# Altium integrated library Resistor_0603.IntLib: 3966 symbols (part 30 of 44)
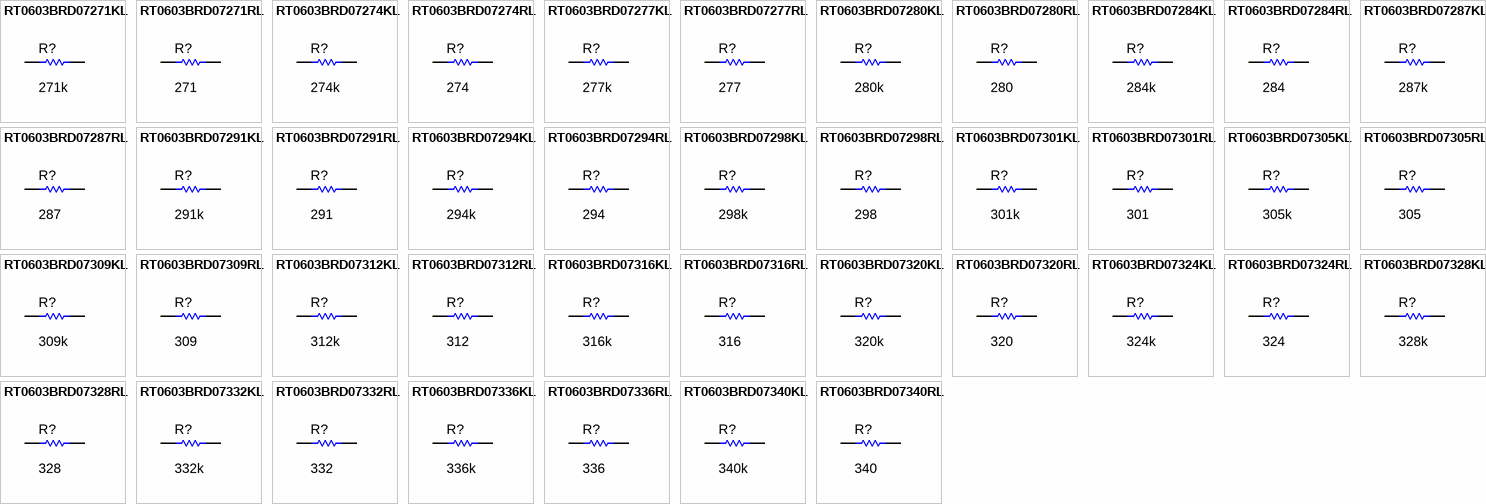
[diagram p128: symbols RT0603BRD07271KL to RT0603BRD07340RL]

## RT0603BRD07274KL
designator R?  ValueDisplayed: 274k  (hidden comment: RT0603BRD07274KL)
RES, 274 k, 0.1%, 0.1 W, 0603; Manufacturer: Yageo America; CompType: Resistor; Value: 274k; Res_ohm: 274000; Tolerance_%: 0.1; Value2: 0.1W; VDC_V: 75; TempCo: 25 ppm/C; SizeArea_mm2: 1.28; SizeX_mm: 1.6; SizeY_mm: 0.8; SizeZ_mm: 1; EIA_Code: E192; U/M: EA; AEC Category: Q200
signal-integrity model Resistor
simulation model Resistor
footprint 0603
footprint 0603M
footprint 0603L
footprint 0603_HV
footprint 0603S
pins: 1, 2

## RT0603BRD07274RL
designator R?  ValueDisplayed: 274  (hidden comment: RT0603BRD07274RL)
RES, 274, 0.1%, 0.1 W, 0603; Manufacturer: Yageo America; CompType: Resistor; Value: 274; Value_Code: 274R; Tolerance_%: 0.1; Value2: 0.1W; VDC_V: 75; TempCo: 25 ppm/C; SizeArea_mm2: 1.28; SizeX_mm: 1.6; SizeY_mm: 0.8; SizeZ_mm: 1; EIA_Code: E192; U/M: EA; AEC Category: Q200
signal-integrity model Resistor
simulation model Resistor
footprint 0603
footprint 0603M
footprint 0603L
footprint 0603_HV
footprint 0603S
pins: 1, 2

## RT0603BRD07277KL
designator R?  ValueDisplayed: 277k  (hidden comment: RT0603BRD07277KL)
RES, 277 k, 0.1%, 0.1 W, 0603; Manufacturer: Yageo America; CompType: Resistor; Value: 277k; Res_ohm: 277000; Tolerance_%: 0.1; Value2: 0.1W; VDC_V: 75; TempCo: 25 ppm/C; SizeArea_mm2: 1.28; SizeX_mm: 1.6; SizeY_mm: 0.8; SizeZ_mm: 1; EIA_Code: E192; U/M: EA; AEC Category: Q200
signal-integrity model Resistor
simulation model Resistor
footprint 0603
footprint 0603M
footprint 0603L
footprint 0603_HV
footprint 0603S
pins: 1, 2

## RT0603BRD07277RL
designator R?  ValueDisplayed: 277  (hidden comment: RT0603BRD07277RL)
RES, 277, 0.1%, 0.1 W, 0603; Manufacturer: Yageo America; CompType: Resistor; Value: 277; Value_Code: 277R; Tolerance_%: 0.1; Value2: 0.1W; VDC_V: 75; TempCo: 25 ppm/C; SizeArea_mm2: 1.28; SizeX_mm: 1.6; SizeY_mm: 0.8; SizeZ_mm: 1; EIA_Code: E192; U/M: EA; AEC Category: Q200
signal-integrity model Resistor
simulation model Resistor
footprint 0603
footprint 0603M
footprint 0603L
footprint 0603_HV
footprint 0603S
pins: 1, 2

## RT0603BRD07280KL
designator R?  ValueDisplayed: 280k  (hidden comment: RT0603BRD07280KL)
RES, 280 k, 0.1%, 0.1 W, 0603; Manufacturer: Yageo America; CompType: Resistor; Value: 280k; Res_ohm: 280000; Tolerance_%: 0.1; Value2: 0.1W; VDC_V: 75; TempCo: 25 ppm/C; SizeArea_mm2: 1.28; SizeX_mm: 1.6; SizeY_mm: 0.8; SizeZ_mm: 1; EIA_Code: E192; U/M: EA; AEC Category: Q200
signal-integrity model Resistor
simulation model Resistor
footprint 0603
footprint 0603M
footprint 0603L
footprint 0603_HV
footprint 0603S
pins: 1, 2

## RT0603BRD07280RL
designator R?  ValueDisplayed: 280  (hidden comment: RT0603BRD07280RL)
RES, 280, 0.1%, 0.1 W, 0603; Manufacturer: Yageo America; CompType: Resistor; Value: 280; Value_Code: 280R; Tolerance_%: 0.1; Value2: 0.1W; VDC_V: 75; TempCo: 25 ppm/C; SizeArea_mm2: 1.28; SizeX_mm: 1.6; SizeY_mm: 0.8; SizeZ_mm: 1; EIA_Code: E192; U/M: EA; AEC Category: Q200
signal-integrity model Resistor
simulation model Resistor
footprint 0603
footprint 0603M
footprint 0603L
footprint 0603_HV
footprint 0603S
pins: 1, 2

## RT0603BRD07284KL
designator R?  ValueDisplayed: 284k  (hidden comment: RT0603BRD07284KL)
RES, 284 k, 0.1%, 0.1 W, 0603; Manufacturer: Yageo America; CompType: Resistor; Value: 284k; Res_ohm: 284000; Tolerance_%: 0.1; Value2: 0.1W; VDC_V: 75; TempCo: 25 ppm/C; SizeArea_mm2: 1.28; SizeX_mm: 1.6; SizeY_mm: 0.8; SizeZ_mm: 1; EIA_Code: E192; U/M: EA; AEC Category: Q200
signal-integrity model Resistor
simulation model Resistor
footprint 0603
footprint 0603M
footprint 0603L
footprint 0603_HV
footprint 0603S
pins: 1, 2

## RT0603BRD07284RL
designator R?  ValueDisplayed: 284  (hidden comment: RT0603BRD07284RL)
RES, 284, 0.1%, 0.1 W, 0603; Manufacturer: Yageo America; CompType: Resistor; Value: 284; Value_Code: 284R; Tolerance_%: 0.1; Value2: 0.1W; VDC_V: 75; TempCo: 25 ppm/C; SizeArea_mm2: 1.28; SizeX_mm: 1.6; SizeY_mm: 0.8; SizeZ_mm: 1; EIA_Code: E192; U/M: EA; AEC Category: Q200
signal-integrity model Resistor
simulation model Resistor
footprint 0603
footprint 0603M
footprint 0603L
footprint 0603_HV
footprint 0603S
pins: 1, 2

## RT0603BRD07287KL
designator R?  ValueDisplayed: 287k  (hidden comment: RT0603BRD07287KL)
RES, 287 k, 0.1%, 0.1 W, 0603; Manufacturer: Yageo America; CompType: Resistor; Value: 287k; Res_ohm: 287000; Tolerance_%: 0.1; Value2: 0.1W; VDC_V: 75; TempCo: 25 ppm/C; SizeArea_mm2: 1.28; SizeX_mm: 1.6; SizeY_mm: 0.8; SizeZ_mm: 1; EIA_Code: E192; U/M: EA; AEC Category: Q200
signal-integrity model Resistor
simulation model Resistor
footprint 0603
footprint 0603M
footprint 0603L
footprint 0603_HV
footprint 0603S
pins: 1, 2

## RT0603BRD07287RL
designator R?  ValueDisplayed: 287  (hidden comment: RT0603BRD07287RL)
RES, 287, 0.1%, 0.1 W, 0603; Manufacturer: Yageo America; CompType: Resistor; Value: 287; Value_Code: 287R; Tolerance_%: 0.1; Value2: 0.1W; VDC_V: 75; TempCo: 25 ppm/C; SizeArea_mm2: 1.28; SizeX_mm: 1.6; SizeY_mm: 0.8; SizeZ_mm: 1; EIA_Code: E192; U/M: EA; AEC Category: Q200
signal-integrity model Resistor
simulation model Resistor
footprint 0603
footprint 0603M
footprint 0603L
footprint 0603_HV
footprint 0603S
pins: 1, 2

## RT0603BRD07291KL
designator R?  ValueDisplayed: 291k  (hidden comment: RT0603BRD07291KL)
RES, 291 k, 0.1%, 0.1 W, 0603; Manufacturer: Yageo America; CompType: Resistor; Value: 291k; Res_ohm: 291000; Tolerance_%: 0.1; Value2: 0.1W; VDC_V: 75; TempCo: 25 ppm/C; SizeArea_mm2: 1.28; SizeX_mm: 1.6; SizeY_mm: 0.8; SizeZ_mm: 1; EIA_Code: E192; U/M: EA; AEC Category: Q200
signal-integrity model Resistor
simulation model Resistor
footprint 0603
footprint 0603M
footprint 0603L
footprint 0603_HV
footprint 0603S
pins: 1, 2

## RT0603BRD07291RL
designator R?  ValueDisplayed: 291  (hidden comment: RT0603BRD07291RL)
RES, 291, 0.1%, 0.1 W, 0603; Manufacturer: Yageo America; CompType: Resistor; Value: 291; Value_Code: 291R; Tolerance_%: 0.1; Value2: 0.1W; VDC_V: 75; TempCo: 25 ppm/C; SizeArea_mm2: 1.28; SizeX_mm: 1.6; SizeY_mm: 0.8; SizeZ_mm: 1; EIA_Code: E192; U/M: EA; AEC Category: Q200
signal-integrity model Resistor
simulation model Resistor
footprint 0603
footprint 0603M
footprint 0603L
footprint 0603_HV
footprint 0603S
pins: 1, 2

## RT0603BRD07294KL
designator R?  ValueDisplayed: 294k  (hidden comment: RT0603BRD07294KL)
RES, 294 k, 0.1%, 0.1 W, 0603; Manufacturer: Yageo America; CompType: Resistor; Value: 294k; Res_ohm: 294000; Tolerance_%: 0.1; Value2: 0.1W; VDC_V: 75; TempCo: 25 ppm/C; SizeArea_mm2: 1.28; SizeX_mm: 1.6; SizeY_mm: 0.8; SizeZ_mm: 1; EIA_Code: E192; U/M: EA; AEC Category: Q200
signal-integrity model Resistor
simulation model Resistor
footprint 0603
footprint 0603M
footprint 0603L
footprint 0603_HV
footprint 0603S
pins: 1, 2

## RT0603BRD07294RL
designator R?  ValueDisplayed: 294  (hidden comment: RT0603BRD07294RL)
RES, 294, 0.1%, 0.1 W, 0603; Manufacturer: Yageo America; CompType: Resistor; Value: 294; Value_Code: 294R; Tolerance_%: 0.1; Value2: 0.1W; VDC_V: 75; TempCo: 25 ppm/C; SizeArea_mm2: 1.28; SizeX_mm: 1.6; SizeY_mm: 0.8; SizeZ_mm: 1; EIA_Code: E192; U/M: EA; AEC Category: Q200
signal-integrity model Resistor
simulation model Resistor
footprint 0603
footprint 0603M
footprint 0603L
footprint 0603_HV
footprint 0603S
pins: 1, 2

## RT0603BRD07298KL
designator R?  ValueDisplayed: 298k  (hidden comment: RT0603BRD07298KL)
RES, 298 k, 0.1%, 0.1 W, 0603; Manufacturer: Yageo America; CompType: Resistor; Value: 298k; Res_ohm: 298000; Tolerance_%: 0.1; Value2: 0.1W; VDC_V: 75; TempCo: 25 ppm/C; SizeArea_mm2: 1.28; SizeX_mm: 1.6; SizeY_mm: 0.8; SizeZ_mm: 1; EIA_Code: E192; U/M: EA; AEC Category: Q200
signal-integrity model Resistor
simulation model Resistor
footprint 0603
footprint 0603M
footprint 0603L
footprint 0603_HV
footprint 0603S
pins: 1, 2

## RT0603BRD07298RL
designator R?  ValueDisplayed: 298  (hidden comment: RT0603BRD07298RL)
RES, 298, 0.1%, 0.1 W, 0603; Manufacturer: Yageo America; CompType: Resistor; Value: 298; Value_Code: 298R; Tolerance_%: 0.1; Value2: 0.1W; VDC_V: 75; TempCo: 25 ppm/C; SizeArea_mm2: 1.28; SizeX_mm: 1.6; SizeY_mm: 0.8; SizeZ_mm: 1; EIA_Code: E192; U/M: EA; AEC Category: Q200
signal-integrity model Resistor
simulation model Resistor
footprint 0603
footprint 0603M
footprint 0603L
footprint 0603_HV
footprint 0603S
pins: 1, 2

## RT0603BRD07301KL
designator R?  ValueDisplayed: 301k  (hidden comment: RT0603BRD07301KL)
RES, 301 k, 0.1%, 0.1 W, 0603; Manufacturer: Yageo America; CompType: Resistor; Value: 301k; Res_ohm: 301000; Tolerance_%: 0.1; Value2: 0.1W; VDC_V: 75; TempCo: 25 ppm/C; SizeArea_mm2: 1.28; SizeX_mm: 1.6; SizeY_mm: 0.8; SizeZ_mm: 1; EIA_Code: E192; U/M: EA; AEC Category: Q200
signal-integrity model Resistor
simulation model Resistor
footprint 0603
footprint 0603M
footprint 0603L
footprint 0603_HV
footprint 0603S
pins: 1, 2

## RT0603BRD07301RL
designator R?  ValueDisplayed: 301  (hidden comment: RT0603BRD07301RL)
RES, 301, 0.1%, 0.1 W, 0603; Manufacturer: Yageo America; CompType: Resistor; Value: 301; Value_Code: 301R; Tolerance_%: 0.1; Value2: 0.1W; VDC_V: 75; TempCo: 25 ppm/C; SizeArea_mm2: 1.28; SizeX_mm: 1.6; SizeY_mm: 0.8; SizeZ_mm: 1; EIA_Code: E192; U/M: EA; AEC Category: Q200
signal-integrity model Resistor
simulation model Resistor
footprint 0603
footprint 0603M
footprint 0603L
footprint 0603_HV
footprint 0603S
pins: 1, 2

## RT0603BRD07305KL
designator R?  ValueDisplayed: 305k  (hidden comment: RT0603BRD07305KL)
RES, 305 k, 0.1%, 0.1 W, 0603; Manufacturer: Yageo America; CompType: Resistor; Value: 305k; Res_ohm: 305000; Tolerance_%: 0.1; Value2: 0.1W; VDC_V: 75; TempCo: 25 ppm/C; SizeArea_mm2: 1.28; SizeX_mm: 1.6; SizeY_mm: 0.8; SizeZ_mm: 1; EIA_Code: E192; U/M: EA; AEC Category: Q200
signal-integrity model Resistor
simulation model Resistor
footprint 0603
footprint 0603M
footprint 0603L
footprint 0603_HV
footprint 0603S
pins: 1, 2

## RT0603BRD07305RL
designator R?  ValueDisplayed: 305  (hidden comment: RT0603BRD07305RL)
RES, 305, 0.1%, 0.1 W, 0603; Manufacturer: Yageo America; CompType: Resistor; Value: 305; Value_Code: 305R; Tolerance_%: 0.1; Value2: 0.1W; VDC_V: 75; TempCo: 25 ppm/C; SizeArea_mm2: 1.28; SizeX_mm: 1.6; SizeY_mm: 0.8; SizeZ_mm: 1; EIA_Code: E192; U/M: EA; AEC Category: Q200
signal-integrity model Resistor
simulation model Resistor
footprint 0603
footprint 0603M
footprint 0603L
footprint 0603_HV
footprint 0603S
pins: 1, 2

## RT0603BRD07309KL
designator R?  ValueDisplayed: 309k  (hidden comment: RT0603BRD07309KL)
RES, 309 k, 0.1%, 0.1 W, 0603; Manufacturer: Yageo America; CompType: Resistor; Value: 309k; Res_ohm: 309000; Tolerance_%: 0.1; Value2: 0.1W; VDC_V: 75; TempCo: 25 ppm/C; SizeArea_mm2: 1.28; SizeX_mm: 1.6; SizeY_mm: 0.8; SizeZ_mm: 1; EIA_Code: E192; U/M: EA; AEC Category: Q200
signal-integrity model Resistor
simulation model Resistor
footprint 0603
footprint 0603M
footprint 0603L
footprint 0603_HV
footprint 0603S
pins: 1, 2

## RT0603BRD07309RL
designator R?  ValueDisplayed: 309  (hidden comment: RT0603BRD07309RL)
RES, 309, 0.1%, 0.1 W, 0603; Manufacturer: Yageo America; CompType: Resistor; Value: 309; Value_Code: 309R; Tolerance_%: 0.1; Value2: 0.1W; VDC_V: 75; TempCo: 25 ppm/C; SizeArea_mm2: 1.28; SizeX_mm: 1.6; SizeY_mm: 0.8; SizeZ_mm: 1; EIA_Code: E192; U/M: EA; AEC Category: Q200
signal-integrity model Resistor
simulation model Resistor
footprint 0603
footprint 0603M
footprint 0603L
footprint 0603_HV
footprint 0603S
pins: 1, 2

## RT0603BRD07312KL
designator R?  ValueDisplayed: 312k  (hidden comment: RT0603BRD07312KL)
RES, 312 k, 0.1%, 0.1 W, 0603; Manufacturer: Yageo America; CompType: Resistor; Value: 312k; Res_ohm: 312000; Tolerance_%: 0.1; Value2: 0.1W; VDC_V: 75; TempCo: 25 ppm/C; SizeArea_mm2: 1.28; SizeX_mm: 1.6; SizeY_mm: 0.8; SizeZ_mm: 1; EIA_Code: E192; U/M: EA; AEC Category: Q200
signal-integrity model Resistor
simulation model Resistor
footprint 0603
footprint 0603M
footprint 0603L
footprint 0603_HV
footprint 0603S
pins: 1, 2

## RT0603BRD07312RL
designator R?  ValueDisplayed: 312  (hidden comment: RT0603BRD07312RL)
RES, 312, 0.1%, 0.1 W, 0603; Manufacturer: Yageo America; CompType: Resistor; Value: 312; Value_Code: 312R; Tolerance_%: 0.1; Value2: 0.1W; VDC_V: 75; TempCo: 25 ppm/C; SizeArea_mm2: 1.28; SizeX_mm: 1.6; SizeY_mm: 0.8; SizeZ_mm: 1; EIA_Code: E192; U/M: EA; AEC Category: Q200
signal-integrity model Resistor
simulation model Resistor
footprint 0603
footprint 0603M
footprint 0603L
footprint 0603_HV
footprint 0603S
pins: 1, 2

## RT0603BRD07316KL
designator R?  ValueDisplayed: 316k  (hidden comment: RT0603BRD07316KL)
RES, 316 k, 0.1%, 0.1 W, 0603; Manufacturer: Yageo America; CompType: Resistor; Value: 316k; Res_ohm: 316000; Tolerance_%: 0.1; Value2: 0.1W; VDC_V: 75; TempCo: 25 ppm/C; SizeArea_mm2: 1.28; SizeX_mm: 1.6; SizeY_mm: 0.8; SizeZ_mm: 1; EIA_Code: E192; U/M: EA; AEC Category: Q200
signal-integrity model Resistor
simulation model Resistor
footprint 0603
footprint 0603M
footprint 0603L
footprint 0603_HV
footprint 0603S
pins: 1, 2

## RT0603BRD07316RL
designator R?  ValueDisplayed: 316  (hidden comment: RT0603BRD07316RL)
RES, 316, 0.1%, 0.1 W, 0603; Manufacturer: Yageo America; CompType: Resistor; Value: 316; Value_Code: 316R; Tolerance_%: 0.1; Value2: 0.1W; VDC_V: 75; TempCo: 25 ppm/C; SizeArea_mm2: 1.28; SizeX_mm: 1.6; SizeY_mm: 0.8; SizeZ_mm: 1; EIA_Code: E192; U/M: EA; AEC Category: Q200
signal-integrity model Resistor
simulation model Resistor
footprint 0603
footprint 0603M
footprint 0603L
footprint 0603_HV
footprint 0603S
pins: 1, 2

## RT0603BRD07320KL
designator R?  ValueDisplayed: 320k  (hidden comment: RT0603BRD07320KL)
RES, 320 k, 0.1%, 0.1 W, 0603; Manufacturer: Yageo America; CompType: Resistor; Value: 320k; Res_ohm: 320000; Tolerance_%: 0.1; Value2: 0.1W; VDC_V: 75; TempCo: 25 ppm/C; SizeArea_mm2: 1.28; SizeX_mm: 1.6; SizeY_mm: 0.8; SizeZ_mm: 1; EIA_Code: E192; U/M: EA; AEC Category: Q200
signal-integrity model Resistor
simulation model Resistor
footprint 0603
footprint 0603M
footprint 0603L
footprint 0603_HV
footprint 0603S
pins: 1, 2

## RT0603BRD07320RL
designator R?  ValueDisplayed: 320  (hidden comment: RT0603BRD07320RL)
RES, 320, 0.1%, 0.1 W, 0603; Manufacturer: Yageo America; CompType: Resistor; Value: 320; Value_Code: 320R; Tolerance_%: 0.1; Value2: 0.1W; VDC_V: 75; TempCo: 25 ppm/C; SizeArea_mm2: 1.28; SizeX_mm: 1.6; SizeY_mm: 0.8; SizeZ_mm: 1; EIA_Code: E192; U/M: EA; AEC Category: Q200
signal-integrity model Resistor
simulation model Resistor
footprint 0603
footprint 0603M
footprint 0603L
footprint 0603_HV
footprint 0603S
pins: 1, 2

## RT0603BRD07324KL
designator R?  ValueDisplayed: 324k  (hidden comment: RT0603BRD07324KL)
RES, 324 k, 0.1%, 0.1 W, 0603; Manufacturer: Yageo America; CompType: Resistor; Value: 324k; Res_ohm: 324000; Tolerance_%: 0.1; Value2: 0.1W; VDC_V: 75; TempCo: 25 ppm/C; SizeArea_mm2: 1.28; SizeX_mm: 1.6; SizeY_mm: 0.8; SizeZ_mm: 1; EIA_Code: E192; U/M: EA; AEC Category: Q200
signal-integrity model Resistor
simulation model Resistor
footprint 0603
footprint 0603M
footprint 0603L
footprint 0603_HV
footprint 0603S
pins: 1, 2

## RT0603BRD07324RL
designator R?  ValueDisplayed: 324  (hidden comment: RT0603BRD07324RL)
RES, 324, 0.1%, 0.1 W, 0603; Manufacturer: Yageo America; CompType: Resistor; Value: 324; Value_Code: 324R; Tolerance_%: 0.1; Value2: 0.1W; VDC_V: 75; TempCo: 25 ppm/C; SizeArea_mm2: 1.28; SizeX_mm: 1.6; SizeY_mm: 0.8; SizeZ_mm: 1; EIA_Code: E192; U/M: EA; AEC Category: Q200
signal-integrity model Resistor
simulation model Resistor
footprint 0603
footprint 0603M
footprint 0603L
footprint 0603_HV
footprint 0603S
pins: 1, 2

## RT0603BRD07328KL
designator R?  ValueDisplayed: 328k  (hidden comment: RT0603BRD07328KL)
RES, 328 k, 0.1%, 0.1 W, 0603; Manufacturer: Yageo America; CompType: Resistor; Value: 328k; Res_ohm: 328000; Tolerance_%: 0.1; Value2: 0.1W; VDC_V: 75; TempCo: 25 ppm/C; SizeArea_mm2: 1.28; SizeX_mm: 1.6; SizeY_mm: 0.8; SizeZ_mm: 1; EIA_Code: E192; U/M: EA; AEC Category: Q200
signal-integrity model Resistor
simulation model Resistor
footprint 0603
footprint 0603M
footprint 0603L
footprint 0603_HV
footprint 0603S
pins: 1, 2

## RT0603BRD07328RL
designator R?  ValueDisplayed: 328  (hidden comment: RT0603BRD07328RL)
RES, 328, 0.1%, 0.1 W, 0603; Manufacturer: Yageo America; CompType: Resistor; Value: 328; Value_Code: 328R; Tolerance_%: 0.1; Value2: 0.1W; VDC_V: 75; TempCo: 25 ppm/C; SizeArea_mm2: 1.28; SizeX_mm: 1.6; SizeY_mm: 0.8; SizeZ_mm: 1; EIA_Code: E192; U/M: EA; AEC Category: Q200
signal-integrity model Resistor
simulation model Resistor
footprint 0603
footprint 0603M
footprint 0603L
footprint 0603_HV
footprint 0603S
pins: 1, 2

## RT0603BRD07332KL
designator R?  ValueDisplayed: 332k  (hidden comment: RT0603BRD07332KL)
RES, 332 k, 0.1%, 0.1 W, 0603; Manufacturer: Yageo America; CompType: Resistor; Value: 332k; Res_ohm: 332000; Tolerance_%: 0.1; Value2: 0.1W; VDC_V: 75; TempCo: 25 ppm/C; SizeArea_mm2: 1.28; SizeX_mm: 1.6; SizeY_mm: 0.8; SizeZ_mm: 1; EIA_Code: E192; U/M: EA; AEC Category: Q200
signal-integrity model Resistor
simulation model Resistor
footprint 0603
footprint 0603M
footprint 0603L
footprint 0603_HV
footprint 0603S
pins: 1, 2

## RT0603BRD07332RL
designator R?  ValueDisplayed: 332  (hidden comment: RT0603BRD07332RL)
RES, 332, 0.1%, 0.1 W, 0603; Manufacturer: Yageo America; CompType: Resistor; Value: 332; Value_Code: 332R; Tolerance_%: 0.1; Value2: 0.1W; VDC_V: 75; TempCo: 25 ppm/C; SizeArea_mm2: 1.28; SizeX_mm: 1.6; SizeY_mm: 0.8; SizeZ_mm: 1; EIA_Code: E192; U/M: EA; AEC Category: Q200
signal-integrity model Resistor
simulation model Resistor
footprint 0603
footprint 0603M
footprint 0603L
footprint 0603_HV
footprint 0603S
pins: 1, 2

## RT0603BRD07336KL
designator R?  ValueDisplayed: 336k  (hidden comment: RT0603BRD07336KL)
RES, 336 k, 0.1%, 0.1 W, 0603; Manufacturer: Yageo America; CompType: Resistor; Value: 336k; Res_ohm: 336000; Tolerance_%: 0.1; Value2: 0.1W; VDC_V: 75; TempCo: 25 ppm/C; SizeArea_mm2: 1.28; SizeX_mm: 1.6; SizeY_mm: 0.8; SizeZ_mm: 1; EIA_Code: E192; U/M: EA; AEC Category: Q200
signal-integrity model Resistor
simulation model Resistor
footprint 0603
footprint 0603M
footprint 0603L
footprint 0603_HV
footprint 0603S
pins: 1, 2

## RT0603BRD07336RL
designator R?  ValueDisplayed: 336  (hidden comment: RT0603BRD07336RL)
RES, 336, 0.1%, 0.1 W, 0603; Manufacturer: Yageo America; CompType: Resistor; Value: 336; Value_Code: 336R; Tolerance_%: 0.1; Value2: 0.1W; VDC_V: 75; TempCo: 25 ppm/C; SizeArea_mm2: 1.28; SizeX_mm: 1.6; SizeY_mm: 0.8; SizeZ_mm: 1; EIA_Code: E192; U/M: EA; AEC Category: Q200
signal-integrity model Resistor
simulation model Resistor
footprint 0603
footprint 0603M
footprint 0603L
footprint 0603_HV
footprint 0603S
pins: 1, 2

## RT0603BRD07340KL
designator R?  ValueDisplayed: 340k  (hidden comment: RT0603BRD07340KL)
RES, 340 k, 0.1%, 0.1 W, 0603; Manufacturer: Yageo America; CompType: Resistor; Value: 340k; Res_ohm: 340000; Tolerance_%: 0.1; Value2: 0.1W; VDC_V: 75; TempCo: 25 ppm/C; SizeArea_mm2: 1.28; SizeX_mm: 1.6; SizeY_mm: 0.8; SizeZ_mm: 1; EIA_Code: E192; U/M: EA; AEC Category: Q200
signal-integrity model Resistor
simulation model Resistor
footprint 0603
footprint 0603M
footprint 0603L
footprint 0603_HV
footprint 0603S
pins: 1, 2

## RT0603BRD07340RL
designator R?  ValueDisplayed: 340  (hidden comment: RT0603BRD07340RL)
RES, 340, 0.1%, 0.1 W, 0603; Manufacturer: Yageo America; CompType: Resistor; Value: 340; Value_Code: 340R; Tolerance_%: 0.1; Value2: 0.1W; VDC_V: 75; TempCo: 25 ppm/C; SizeArea_mm2: 1.28; SizeX_mm: 1.6; SizeY_mm: 0.8; SizeZ_mm: 1; EIA_Code: E192; U/M: EA; AEC Category: Q200
signal-integrity model Resistor
simulation model Resistor
footprint 0603
footprint 0603M
footprint 0603L
footprint 0603_HV
footprint 0603S
pins: 1, 2

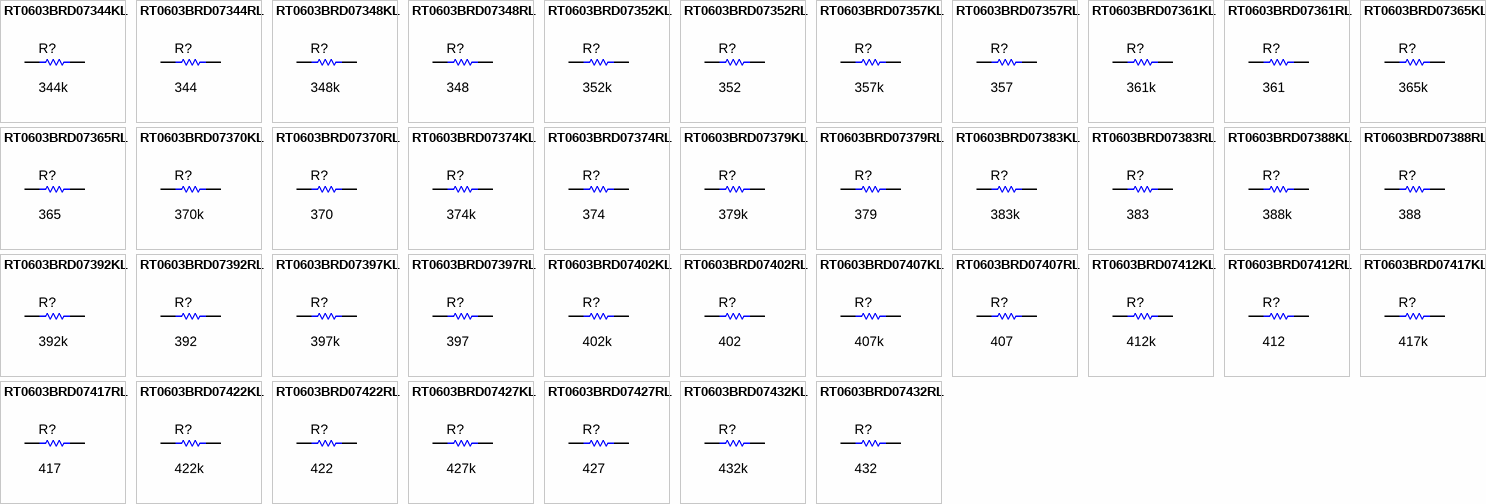
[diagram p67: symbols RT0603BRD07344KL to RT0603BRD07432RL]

## RT0603BRD07344KL
designator R?  ValueDisplayed: 344k  (hidden comment: RT0603BRD07344KL)
RES, 344 k, 0.1%, 0.1 W, 0603; Manufacturer: Yageo America; CompType: Resistor; Value: 344k; Res_ohm: 344000; Tolerance_%: 0.1; Value2: 0.1W; VDC_V: 75; TempCo: 25 ppm/C; SizeArea_mm2: 1.28; SizeX_mm: 1.6; SizeY_mm: 0.8; SizeZ_mm: 1; EIA_Code: E192; U/M: EA; AEC Category: Q200
signal-integrity model Resistor
simulation model Resistor
footprint 0603
footprint 0603M
footprint 0603L
footprint 0603_HV
footprint 0603S
pins: 1, 2

## RT0603BRD07344RL
designator R?  ValueDisplayed: 344  (hidden comment: RT0603BRD07344RL)
RES, 344, 0.1%, 0.1 W, 0603; Manufacturer: Yageo America; CompType: Resistor; Value: 344; Value_Code: 344R; Tolerance_%: 0.1; Value2: 0.1W; VDC_V: 75; TempCo: 25 ppm/C; SizeArea_mm2: 1.28; SizeX_mm: 1.6; SizeY_mm: 0.8; SizeZ_mm: 1; EIA_Code: E192; U/M: EA; AEC Category: Q200
signal-integrity model Resistor
simulation model Resistor
footprint 0603
footprint 0603M
footprint 0603L
footprint 0603_HV
footprint 0603S
pins: 1, 2

## RT0603BRD07348KL
designator R?  ValueDisplayed: 348k  (hidden comment: RT0603BRD07348KL)
RES, 348 k, 0.1%, 0.1 W, 0603; Manufacturer: Yageo America; CompType: Resistor; Value: 348k; Res_ohm: 348000; Tolerance_%: 0.1; Value2: 0.1W; VDC_V: 75; TempCo: 25 ppm/C; SizeArea_mm2: 1.28; SizeX_mm: 1.6; SizeY_mm: 0.8; SizeZ_mm: 1; EIA_Code: E192; U/M: EA; AEC Category: Q200
signal-integrity model Resistor
simulation model Resistor
footprint 0603
footprint 0603M
footprint 0603L
footprint 0603_HV
footprint 0603S
pins: 1, 2

## RT0603BRD07348RL
designator R?  ValueDisplayed: 348  (hidden comment: RT0603BRD07348RL)
RES, 348, 0.1%, 0.1 W, 0603; Manufacturer: Yageo America; CompType: Resistor; Value: 348; Value_Code: 348R; Tolerance_%: 0.1; Value2: 0.1W; VDC_V: 75; TempCo: 25 ppm/C; SizeArea_mm2: 1.28; SizeX_mm: 1.6; SizeY_mm: 0.8; SizeZ_mm: 1; EIA_Code: E192; U/M: EA; AEC Category: Q200
signal-integrity model Resistor
simulation model Resistor
footprint 0603
footprint 0603M
footprint 0603L
footprint 0603_HV
footprint 0603S
pins: 1, 2

## RT0603BRD07352KL
designator R?  ValueDisplayed: 352k  (hidden comment: RT0603BRD07352KL)
RES, 352 k, 0.1%, 0.1 W, 0603; Manufacturer: Yageo America; CompType: Resistor; Value: 352k; Res_ohm: 352000; Tolerance_%: 0.1; Value2: 0.1W; VDC_V: 75; TempCo: 25 ppm/C; SizeArea_mm2: 1.28; SizeX_mm: 1.6; SizeY_mm: 0.8; SizeZ_mm: 1; EIA_Code: E192; U/M: EA; AEC Category: Q200
signal-integrity model Resistor
simulation model Resistor
footprint 0603
footprint 0603M
footprint 0603L
footprint 0603_HV
footprint 0603S
pins: 1, 2

## RT0603BRD07352RL
designator R?  ValueDisplayed: 352  (hidden comment: RT0603BRD07352RL)
RES, 352, 0.1%, 0.1 W, 0603; Manufacturer: Yageo America; CompType: Resistor; Value: 352; Value_Code: 352R; Tolerance_%: 0.1; Value2: 0.1W; VDC_V: 75; TempCo: 25 ppm/C; SizeArea_mm2: 1.28; SizeX_mm: 1.6; SizeY_mm: 0.8; SizeZ_mm: 1; EIA_Code: E192; U/M: EA; AEC Category: Q200
signal-integrity model Resistor
simulation model Resistor
footprint 0603
footprint 0603M
footprint 0603L
footprint 0603_HV
footprint 0603S
pins: 1, 2

## RT0603BRD07357KL
designator R?  ValueDisplayed: 357k  (hidden comment: RT0603BRD07357KL)
RES, 357 k, 0.1%, 0.1 W, 0603; Manufacturer: Yageo America; CompType: Resistor; Value: 357k; Res_ohm: 357000; Tolerance_%: 0.1; Value2: 0.1W; VDC_V: 75; TempCo: 25 ppm/C; SizeArea_mm2: 1.28; SizeX_mm: 1.6; SizeY_mm: 0.8; SizeZ_mm: 1; EIA_Code: E192; U/M: EA; AEC Category: Q200
signal-integrity model Resistor
simulation model Resistor
footprint 0603
footprint 0603M
footprint 0603L
footprint 0603_HV
footprint 0603S
pins: 1, 2

## RT0603BRD07357RL
designator R?  ValueDisplayed: 357  (hidden comment: RT0603BRD07357RL)
RES, 357, 0.1%, 0.1 W, 0603; Manufacturer: Yageo America; CompType: Resistor; Value: 357; Value_Code: 357R; Tolerance_%: 0.1; Value2: 0.1W; VDC_V: 75; TempCo: 25 ppm/C; SizeArea_mm2: 1.28; SizeX_mm: 1.6; SizeY_mm: 0.8; SizeZ_mm: 1; EIA_Code: E192; U/M: EA; AEC Category: Q200
signal-integrity model Resistor
simulation model Resistor
footprint 0603
footprint 0603M
footprint 0603L
footprint 0603_HV
footprint 0603S
pins: 1, 2

## RT0603BRD07361KL
designator R?  ValueDisplayed: 361k  (hidden comment: RT0603BRD07361KL)
RES, 361 k, 0.1%, 0.1 W, 0603; Manufacturer: Yageo America; CompType: Resistor; Value: 361k; Res_ohm: 361000; Tolerance_%: 0.1; Value2: 0.1W; VDC_V: 75; TempCo: 25 ppm/C; SizeArea_mm2: 1.28; SizeX_mm: 1.6; SizeY_mm: 0.8; SizeZ_mm: 1; EIA_Code: E192; U/M: EA; AEC Category: Q200
signal-integrity model Resistor
simulation model Resistor
footprint 0603
footprint 0603M
footprint 0603L
footprint 0603_HV
footprint 0603S
pins: 1, 2

## RT0603BRD07361RL
designator R?  ValueDisplayed: 361  (hidden comment: RT0603BRD07361RL)
RES, 361, 0.1%, 0.1 W, 0603; Manufacturer: Yageo America; CompType: Resistor; Value: 361; Value_Code: 361R; Tolerance_%: 0.1; Value2: 0.1W; VDC_V: 75; TempCo: 25 ppm/C; SizeArea_mm2: 1.28; SizeX_mm: 1.6; SizeY_mm: 0.8; SizeZ_mm: 1; EIA_Code: E192; U/M: EA; AEC Category: Q200
signal-integrity model Resistor
simulation model Resistor
footprint 0603
footprint 0603M
footprint 0603L
footprint 0603_HV
footprint 0603S
pins: 1, 2

## RT0603BRD07365KL
designator R?  ValueDisplayed: 365k  (hidden comment: RT0603BRD07365KL)
RES, 365 k, 0.1%, 0.1 W, 0603; Manufacturer: Yageo America; CompType: Resistor; Value: 365k; Res_ohm: 365000; Tolerance_%: 0.1; Value2: 0.1W; VDC_V: 75; TempCo: 25 ppm/C; SizeArea_mm2: 1.28; SizeX_mm: 1.6; SizeY_mm: 0.8; SizeZ_mm: 1; EIA_Code: E192; U/M: EA; AEC Category: Q200
signal-integrity model Resistor
simulation model Resistor
footprint 0603
footprint 0603M
footprint 0603L
footprint 0603_HV
footprint 0603S
pins: 1, 2

## RT0603BRD07365RL
designator R?  ValueDisplayed: 365  (hidden comment: RT0603BRD07365RL)
RES, 365, 0.1%, 0.1 W, 0603; Manufacturer: Yageo America; CompType: Resistor; Value: 365; Value_Code: 365R; Tolerance_%: 0.1; Value2: 0.1W; VDC_V: 75; TempCo: 25 ppm/C; SizeArea_mm2: 1.28; SizeX_mm: 1.6; SizeY_mm: 0.8; SizeZ_mm: 1; EIA_Code: E192; U/M: EA; AEC Category: Q200
signal-integrity model Resistor
simulation model Resistor
footprint 0603
footprint 0603M
footprint 0603L
footprint 0603_HV
footprint 0603S
pins: 1, 2

## RT0603BRD07370KL
designator R?  ValueDisplayed: 370k  (hidden comment: RT0603BRD07370KL)
RES, 370 k, 0.1%, 0.1 W, 0603; Manufacturer: Yageo America; CompType: Resistor; Value: 370k; Res_ohm: 370000; Tolerance_%: 0.1; Value2: 0.1W; VDC_V: 75; TempCo: 25 ppm/C; SizeArea_mm2: 1.28; SizeX_mm: 1.6; SizeY_mm: 0.8; SizeZ_mm: 1; EIA_Code: E192; U/M: EA; AEC Category: Q200
signal-integrity model Resistor
simulation model Resistor
footprint 0603
footprint 0603M
footprint 0603L
footprint 0603_HV
footprint 0603S
pins: 1, 2

## RT0603BRD07370RL
designator R?  ValueDisplayed: 370  (hidden comment: RT0603BRD07370RL)
RES, 370, 0.1%, 0.1 W, 0603; Manufacturer: Yageo America; CompType: Resistor; Value: 370; Value_Code: 370R; Tolerance_%: 0.1; Value2: 0.1W; VDC_V: 75; TempCo: 25 ppm/C; SizeArea_mm2: 1.28; SizeX_mm: 1.6; SizeY_mm: 0.8; SizeZ_mm: 1; EIA_Code: E192; U/M: EA; AEC Category: Q200
signal-integrity model Resistor
simulation model Resistor
footprint 0603
footprint 0603M
footprint 0603L
footprint 0603_HV
footprint 0603S
pins: 1, 2

## RT0603BRD07374KL
designator R?  ValueDisplayed: 374k  (hidden comment: RT0603BRD07374KL)
RES, 374 k, 0.1%, 0.1 W, 0603; Manufacturer: Yageo America; CompType: Resistor; Value: 374k; Res_ohm: 374000; Tolerance_%: 0.1; Value2: 0.1W; VDC_V: 75; TempCo: 25 ppm/C; SizeArea_mm2: 1.28; SizeX_mm: 1.6; SizeY_mm: 0.8; SizeZ_mm: 1; EIA_Code: E192; U/M: EA; AEC Category: Q200
signal-integrity model Resistor
simulation model Resistor
footprint 0603
footprint 0603M
footprint 0603L
footprint 0603_HV
footprint 0603S
pins: 1, 2

## RT0603BRD07374RL
designator R?  ValueDisplayed: 374  (hidden comment: RT0603BRD07374RL)
RES, 374, 0.1%, 0.1 W, 0603; Manufacturer: Yageo America; CompType: Resistor; Value: 374; Value_Code: 374R; Tolerance_%: 0.1; Value2: 0.1W; VDC_V: 75; TempCo: 25 ppm/C; SizeArea_mm2: 1.28; SizeX_mm: 1.6; SizeY_mm: 0.8; SizeZ_mm: 1; EIA_Code: E192; U/M: EA; AEC Category: Q200
signal-integrity model Resistor
simulation model Resistor
footprint 0603
footprint 0603M
footprint 0603L
footprint 0603_HV
footprint 0603S
pins: 1, 2

## RT0603BRD07379KL
designator R?  ValueDisplayed: 379k  (hidden comment: RT0603BRD07379KL)
RES, 379 k, 0.1%, 0.1 W, 0603; Manufacturer: Yageo America; CompType: Resistor; Value: 379k; Res_ohm: 379000; Tolerance_%: 0.1; Value2: 0.1W; VDC_V: 75; TempCo: 25 ppm/C; SizeArea_mm2: 1.28; SizeX_mm: 1.6; SizeY_mm: 0.8; SizeZ_mm: 1; EIA_Code: E192; U/M: EA; AEC Category: Q200
signal-integrity model Resistor
simulation model Resistor
footprint 0603
footprint 0603M
footprint 0603L
footprint 0603_HV
footprint 0603S
pins: 1, 2

## RT0603BRD07379RL
designator R?  ValueDisplayed: 379  (hidden comment: RT0603BRD07379RL)
RES, 379, 0.1%, 0.1 W, 0603; Manufacturer: Yageo America; CompType: Resistor; Value: 379; Value_Code: 379R; Tolerance_%: 0.1; Value2: 0.1W; VDC_V: 75; TempCo: 25 ppm/C; SizeArea_mm2: 1.28; SizeX_mm: 1.6; SizeY_mm: 0.8; SizeZ_mm: 1; EIA_Code: E192; U/M: EA; AEC Category: Q200
signal-integrity model Resistor
simulation model Resistor
footprint 0603
footprint 0603M
footprint 0603L
footprint 0603_HV
footprint 0603S
pins: 1, 2

## RT0603BRD07383KL
designator R?  ValueDisplayed: 383k  (hidden comment: RT0603BRD07383KL)
RES, 383 k, 0.1%, 0.1 W, 0603; Manufacturer: Yageo America; CompType: Resistor; Value: 383k; Res_ohm: 383000; Tolerance_%: 0.1; Value2: 0.1W; VDC_V: 75; TempCo: 25 ppm/C; SizeArea_mm2: 1.28; SizeX_mm: 1.6; SizeY_mm: 0.8; SizeZ_mm: 1; EIA_Code: E192; U/M: EA; AEC Category: Q200
signal-integrity model Resistor
simulation model Resistor
footprint 0603
footprint 0603M
footprint 0603L
footprint 0603_HV
footprint 0603S
pins: 1, 2

## RT0603BRD07383RL
designator R?  ValueDisplayed: 383  (hidden comment: RT0603BRD07383RL)
RES, 383, 0.1%, 0.1 W, 0603; Manufacturer: Yageo America; CompType: Resistor; Value: 383; Value_Code: 383R; Tolerance_%: 0.1; Value2: 0.1W; VDC_V: 75; TempCo: 25 ppm/C; SizeArea_mm2: 1.28; SizeX_mm: 1.6; SizeY_mm: 0.8; SizeZ_mm: 1; EIA_Code: E192; U/M: EA; AEC Category: Q200
signal-integrity model Resistor
simulation model Resistor
footprint 0603
footprint 0603M
footprint 0603L
footprint 0603_HV
footprint 0603S
pins: 1, 2

## RT0603BRD07388KL
designator R?  ValueDisplayed: 388k  (hidden comment: RT0603BRD07388KL)
RES, 388 k, 0.1%, 0.1 W, 0603; Manufacturer: Yageo America; CompType: Resistor; Value: 388k; Res_ohm: 388000; Tolerance_%: 0.1; Value2: 0.1W; VDC_V: 75; TempCo: 25 ppm/C; SizeArea_mm2: 1.28; SizeX_mm: 1.6; SizeY_mm: 0.8; SizeZ_mm: 1; EIA_Code: E192; U/M: EA; AEC Category: Q200
signal-integrity model Resistor
simulation model Resistor
footprint 0603
footprint 0603M
footprint 0603L
footprint 0603_HV
footprint 0603S
pins: 1, 2

## RT0603BRD07388RL
designator R?  ValueDisplayed: 388  (hidden comment: RT0603BRD07388RL)
RES, 388, 0.1%, 0.1 W, 0603; Manufacturer: Yageo America; CompType: Resistor; Value: 388; Value_Code: 388R; Tolerance_%: 0.1; Value2: 0.1W; VDC_V: 75; TempCo: 25 ppm/C; SizeArea_mm2: 1.28; SizeX_mm: 1.6; SizeY_mm: 0.8; SizeZ_mm: 1; EIA_Code: E192; U/M: EA; AEC Category: Q200
signal-integrity model Resistor
simulation model Resistor
footprint 0603
footprint 0603M
footprint 0603L
footprint 0603_HV
footprint 0603S
pins: 1, 2

## RT0603BRD07392KL
designator R?  ValueDisplayed: 392k  (hidden comment: RT0603BRD07392KL)
RES, 392 k, 0.1%, 0.1 W, 0603; Manufacturer: Yageo America; CompType: Resistor; Value: 392k; Res_ohm: 392000; Tolerance_%: 0.1; Value2: 0.1W; VDC_V: 75; TempCo: 25 ppm/C; SizeArea_mm2: 1.28; SizeX_mm: 1.6; SizeY_mm: 0.8; SizeZ_mm: 1; EIA_Code: E192; U/M: EA; AEC Category: Q200
signal-integrity model Resistor
simulation model Resistor
footprint 0603
footprint 0603M
footprint 0603L
footprint 0603_HV
footprint 0603S
pins: 1, 2

## RT0603BRD07392RL
designator R?  ValueDisplayed: 392  (hidden comment: RT0603BRD07392RL)
RES, 392, 0.1%, 0.1 W, 0603; Manufacturer: Yageo America; CompType: Resistor; Value: 392; Value_Code: 392R; Tolerance_%: 0.1; Value2: 0.1W; VDC_V: 75; TempCo: 25 ppm/C; SizeArea_mm2: 1.28; SizeX_mm: 1.6; SizeY_mm: 0.8; SizeZ_mm: 1; EIA_Code: E192; U/M: EA; AEC Category: Q200
signal-integrity model Resistor
simulation model Resistor
footprint 0603
footprint 0603M
footprint 0603L
footprint 0603_HV
footprint 0603S
pins: 1, 2

## RT0603BRD07397KL
designator R?  ValueDisplayed: 397k  (hidden comment: RT0603BRD07397KL)
RES, 397 k, 0.1%, 0.1 W, 0603; Manufacturer: Yageo America; CompType: Resistor; Value: 397k; Res_ohm: 397000; Tolerance_%: 0.1; Value2: 0.1W; VDC_V: 75; TempCo: 25 ppm/C; SizeArea_mm2: 1.28; SizeX_mm: 1.6; SizeY_mm: 0.8; SizeZ_mm: 1; EIA_Code: E192; U/M: EA; AEC Category: Q200
signal-integrity model Resistor
simulation model Resistor
footprint 0603
footprint 0603M
footprint 0603L
footprint 0603_HV
footprint 0603S
pins: 1, 2

## RT0603BRD07397RL
designator R?  ValueDisplayed: 397  (hidden comment: RT0603BRD07397RL)
RES, 397, 0.1%, 0.1 W, 0603; Manufacturer: Yageo America; CompType: Resistor; Value: 397; Value_Code: 397R; Tolerance_%: 0.1; Value2: 0.1W; VDC_V: 75; TempCo: 25 ppm/C; SizeArea_mm2: 1.28; SizeX_mm: 1.6; SizeY_mm: 0.8; SizeZ_mm: 1; EIA_Code: E192; U/M: EA; AEC Category: Q200
signal-integrity model Resistor
simulation model Resistor
footprint 0603
footprint 0603M
footprint 0603L
footprint 0603_HV
footprint 0603S
pins: 1, 2

## RT0603BRD07402KL
designator R?  ValueDisplayed: 402k  (hidden comment: RT0603BRD07402KL)
RES, 402 k, 0.1%, 0.1 W, 0603; Manufacturer: Yageo America; CompType: Resistor; Value: 402k; Res_ohm: 402000; Tolerance_%: 0.1; Value2: 0.1W; VDC_V: 75; TempCo: 25 ppm/C; SizeArea_mm2: 1.28; SizeX_mm: 1.6; SizeY_mm: 0.8; SizeZ_mm: 1; EIA_Code: E192; U/M: EA; AEC Category: Q200
signal-integrity model Resistor
simulation model Resistor
footprint 0603
footprint 0603M
footprint 0603L
footprint 0603_HV
footprint 0603S
pins: 1, 2

## RT0603BRD07402RL
designator R?  ValueDisplayed: 402  (hidden comment: RT0603BRD07402RL)
RES, 402, 0.1%, 0.1 W, 0603; Manufacturer: Yageo America; CompType: Resistor; Value: 402; Value_Code: 402R; Tolerance_%: 0.1; Value2: 0.1W; VDC_V: 75; TempCo: 25 ppm/C; SizeArea_mm2: 1.28; SizeX_mm: 1.6; SizeY_mm: 0.8; SizeZ_mm: 1; EIA_Code: E192; U/M: EA; AEC Category: Q200
signal-integrity model Resistor
simulation model Resistor
footprint 0603
footprint 0603M
footprint 0603L
footprint 0603_HV
footprint 0603S
pins: 1, 2

## RT0603BRD07407KL
designator R?  ValueDisplayed: 407k  (hidden comment: RT0603BRD07407KL)
RES, 407 k, 0.1%, 0.1 W, 0603; Manufacturer: Yageo America; CompType: Resistor; Value: 407k; Res_ohm: 407000; Tolerance_%: 0.1; Value2: 0.1W; VDC_V: 75; TempCo: 25 ppm/C; SizeArea_mm2: 1.28; SizeX_mm: 1.6; SizeY_mm: 0.8; SizeZ_mm: 1; EIA_Code: E192; U/M: EA; AEC Category: Q200
signal-integrity model Resistor
simulation model Resistor
footprint 0603
footprint 0603M
footprint 0603L
footprint 0603_HV
footprint 0603S
pins: 1, 2

## RT0603BRD07407RL
designator R?  ValueDisplayed: 407  (hidden comment: RT0603BRD07407RL)
RES, 407, 0.1%, 0.1 W, 0603; Manufacturer: Yageo America; CompType: Resistor; Value: 407; Value_Code: 407R; Tolerance_%: 0.1; Value2: 0.1W; VDC_V: 75; TempCo: 25 ppm/C; SizeArea_mm2: 1.28; SizeX_mm: 1.6; SizeY_mm: 0.8; SizeZ_mm: 1; EIA_Code: E192; U/M: EA; AEC Category: Q200
signal-integrity model Resistor
simulation model Resistor
footprint 0603
footprint 0603M
footprint 0603L
footprint 0603_HV
footprint 0603S
pins: 1, 2

## RT0603BRD07412KL
designator R?  ValueDisplayed: 412k  (hidden comment: RT0603BRD07412KL)
RES, 412 k, 0.1%, 0.1 W, 0603; Manufacturer: Yageo America; CompType: Resistor; Value: 412k; Res_ohm: 412000; Tolerance_%: 0.1; Value2: 0.1W; VDC_V: 75; TempCo: 25 ppm/C; SizeArea_mm2: 1.28; SizeX_mm: 1.6; SizeY_mm: 0.8; SizeZ_mm: 1; EIA_Code: E192; U/M: EA; AEC Category: Q200
signal-integrity model Resistor
simulation model Resistor
footprint 0603
footprint 0603M
footprint 0603L
footprint 0603_HV
footprint 0603S
pins: 1, 2

## RT0603BRD07412RL
designator R?  ValueDisplayed: 412  (hidden comment: RT0603BRD07412RL)
RES, 412, 0.1%, 0.1 W, 0603; Manufacturer: Yageo America; CompType: Resistor; Value: 412; Value_Code: 412R; Tolerance_%: 0.1; Value2: 0.1W; VDC_V: 75; TempCo: 25 ppm/C; SizeArea_mm2: 1.28; SizeX_mm: 1.6; SizeY_mm: 0.8; SizeZ_mm: 1; EIA_Code: E192; U/M: EA; AEC Category: Q200
signal-integrity model Resistor
simulation model Resistor
footprint 0603
footprint 0603M
footprint 0603L
footprint 0603_HV
footprint 0603S
pins: 1, 2

## RT0603BRD07417KL
designator R?  ValueDisplayed: 417k  (hidden comment: RT0603BRD07417KL)
RES, 417 k, 0.1%, 0.1 W, 0603; Manufacturer: Yageo America; CompType: Resistor; Value: 417k; Res_ohm: 417000; Tolerance_%: 0.1; Value2: 0.1W; VDC_V: 75; TempCo: 25 ppm/C; SizeArea_mm2: 1.28; SizeX_mm: 1.6; SizeY_mm: 0.8; SizeZ_mm: 1; EIA_Code: E192; U/M: EA; AEC Category: Q200
signal-integrity model Resistor
simulation model Resistor
footprint 0603
footprint 0603M
footprint 0603L
footprint 0603_HV
footprint 0603S
pins: 1, 2

## RT0603BRD07417RL
designator R?  ValueDisplayed: 417  (hidden comment: RT0603BRD07417RL)
RES, 417, 0.1%, 0.1 W, 0603; Manufacturer: Yageo America; CompType: Resistor; Value: 417; Value_Code: 417R; Tolerance_%: 0.1; Value2: 0.1W; VDC_V: 75; TempCo: 25 ppm/C; SizeArea_mm2: 1.28; SizeX_mm: 1.6; SizeY_mm: 0.8; SizeZ_mm: 1; EIA_Code: E192; U/M: EA; AEC Category: Q200
signal-integrity model Resistor
simulation model Resistor
footprint 0603
footprint 0603M
footprint 0603L
footprint 0603_HV
footprint 0603S
pins: 1, 2

## RT0603BRD07422KL
designator R?  ValueDisplayed: 422k  (hidden comment: RT0603BRD07422KL)
RES, 422 k, 0.1%, 0.1 W, 0603; Manufacturer: Yageo America; CompType: Resistor; Value: 422k; Res_ohm: 422000; Tolerance_%: 0.1; Value2: 0.1W; VDC_V: 75; TempCo: 25 ppm/C; SizeArea_mm2: 1.28; SizeX_mm: 1.6; SizeY_mm: 0.8; SizeZ_mm: 1; EIA_Code: E192; U/M: EA; AEC Category: Q200
signal-integrity model Resistor
simulation model Resistor
footprint 0603
footprint 0603M
footprint 0603L
footprint 0603_HV
footprint 0603S
pins: 1, 2

## RT0603BRD07422RL
designator R?  ValueDisplayed: 422  (hidden comment: RT0603BRD07422RL)
RES, 422, 0.1%, 0.1 W, 0603; Manufacturer: Yageo America; CompType: Resistor; Value: 422; Value_Code: 422R; Tolerance_%: 0.1; Value2: 0.1W; VDC_V: 75; TempCo: 25 ppm/C; SizeArea_mm2: 1.28; SizeX_mm: 1.6; SizeY_mm: 0.8; SizeZ_mm: 1; EIA_Code: E192; U/M: EA; AEC Category: Q200
signal-integrity model Resistor
simulation model Resistor
footprint 0603
footprint 0603M
footprint 0603L
footprint 0603_HV
footprint 0603S
pins: 1, 2

## RT0603BRD07427KL
designator R?  ValueDisplayed: 427k  (hidden comment: RT0603BRD07427KL)
RES, 427 k, 0.1%, 0.1 W, 0603; Manufacturer: Yageo America; CompType: Resistor; Value: 427k; Res_ohm: 427000; Tolerance_%: 0.1; Value2: 0.1W; VDC_V: 75; TempCo: 25 ppm/C; SizeArea_mm2: 1.28; SizeX_mm: 1.6; SizeY_mm: 0.8; SizeZ_mm: 1; EIA_Code: E192; U/M: EA; AEC Category: Q200
signal-integrity model Resistor
simulation model Resistor
footprint 0603
footprint 0603M
footprint 0603L
footprint 0603_HV
footprint 0603S
pins: 1, 2

## RT0603BRD07427RL
designator R?  ValueDisplayed: 427  (hidden comment: RT0603BRD07427RL)
RES, 427, 0.1%, 0.1 W, 0603; Manufacturer: Yageo America; CompType: Resistor; Value: 427; Value_Code: 427R; Tolerance_%: 0.1; Value2: 0.1W; VDC_V: 75; TempCo: 25 ppm/C; SizeArea_mm2: 1.28; SizeX_mm: 1.6; SizeY_mm: 0.8; SizeZ_mm: 1; EIA_Code: E192; U/M: EA; AEC Category: Q200
signal-integrity model Resistor
simulation model Resistor
footprint 0603
footprint 0603M
footprint 0603L
footprint 0603_HV
footprint 0603S
pins: 1, 2

## RT0603BRD07432KL
designator R?  ValueDisplayed: 432k  (hidden comment: RT0603BRD07432KL)
RES, 432 k, 0.1%, 0.1 W, 0603; Manufacturer: Yageo America; CompType: Resistor; Value: 432k; Res_ohm: 432000; Tolerance_%: 0.1; Value2: 0.1W; VDC_V: 75; TempCo: 25 ppm/C; SizeArea_mm2: 1.28; SizeX_mm: 1.6; SizeY_mm: 0.8; SizeZ_mm: 1; EIA_Code: E192; U/M: EA; AEC Category: Q200
signal-integrity model Resistor
simulation model Resistor
footprint 0603
footprint 0603M
footprint 0603L
footprint 0603_HV
footprint 0603S
pins: 1, 2

## RT0603BRD07432RL
designator R?  ValueDisplayed: 432  (hidden comment: RT0603BRD07432RL)
RES, 432, 0.1%, 0.1 W, 0603; Manufacturer: Yageo America; CompType: Resistor; Value: 432; Value_Code: 432R; Tolerance_%: 0.1; Value2: 0.1W; VDC_V: 75; TempCo: 25 ppm/C; SizeArea_mm2: 1.28; SizeX_mm: 1.6; SizeY_mm: 0.8; SizeZ_mm: 1; EIA_Code: E192; U/M: EA; AEC Category: Q200
signal-integrity model Resistor
simulation model Resistor
footprint 0603
footprint 0603M
footprint 0603L
footprint 0603_HV
footprint 0603S
pins: 1, 2

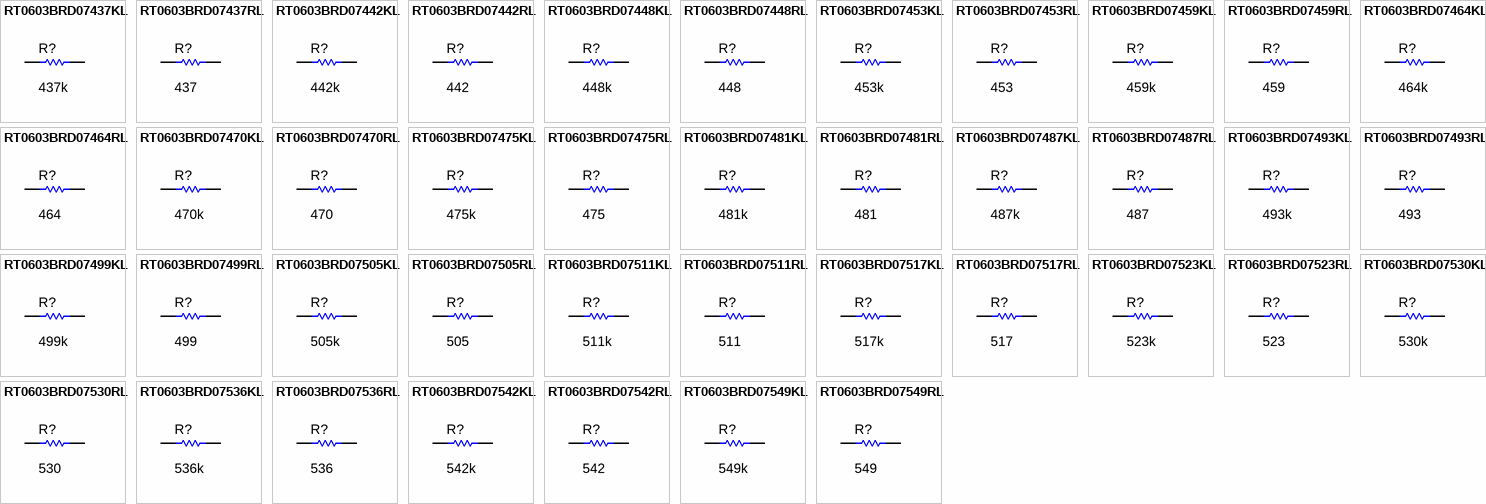
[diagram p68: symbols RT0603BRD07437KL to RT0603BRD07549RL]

## RT0603BRD07437KL
designator R?  ValueDisplayed: 437k  (hidden comment: RT0603BRD07437KL)
RES, 437 k, 0.1%, 0.1 W, 0603; Manufacturer: Yageo America; CompType: Resistor; Value: 437k; Res_ohm: 437000; Tolerance_%: 0.1; Value2: 0.1W; VDC_V: 75; TempCo: 25 ppm/C; SizeArea_mm2: 1.28; SizeX_mm: 1.6; SizeY_mm: 0.8; SizeZ_mm: 1; EIA_Code: E192; U/M: EA; AEC Category: Q200
signal-integrity model Resistor
simulation model Resistor
footprint 0603
footprint 0603M
footprint 0603L
footprint 0603_HV
footprint 0603S
pins: 1, 2

## RT0603BRD07437RL
designator R?  ValueDisplayed: 437  (hidden comment: RT0603BRD07437RL)
RES, 437, 0.1%, 0.1 W, 0603; Manufacturer: Yageo America; CompType: Resistor; Value: 437; Value_Code: 437R; Tolerance_%: 0.1; Value2: 0.1W; VDC_V: 75; TempCo: 25 ppm/C; SizeArea_mm2: 1.28; SizeX_mm: 1.6; SizeY_mm: 0.8; SizeZ_mm: 1; EIA_Code: E192; U/M: EA; AEC Category: Q200
signal-integrity model Resistor
simulation model Resistor
footprint 0603
footprint 0603M
footprint 0603L
footprint 0603_HV
footprint 0603S
pins: 1, 2

## RT0603BRD07442KL
designator R?  ValueDisplayed: 442k  (hidden comment: RT0603BRD07442KL)
RES, 442 k, 0.1%, 0.1 W, 0603; Manufacturer: Yageo America; CompType: Resistor; Value: 442k; Res_ohm: 442000; Tolerance_%: 0.1; Value2: 0.1W; VDC_V: 75; TempCo: 25 ppm/C; SizeArea_mm2: 1.28; SizeX_mm: 1.6; SizeY_mm: 0.8; SizeZ_mm: 1; EIA_Code: E192; U/M: EA; AEC Category: Q200
signal-integrity model Resistor
simulation model Resistor
footprint 0603
footprint 0603M
footprint 0603L
footprint 0603_HV
footprint 0603S
pins: 1, 2

## RT0603BRD07442RL
designator R?  ValueDisplayed: 442  (hidden comment: RT0603BRD07442RL)
RES, 442, 0.1%, 0.1 W, 0603; Manufacturer: Yageo America; CompType: Resistor; Value: 442; Value_Code: 442R; Tolerance_%: 0.1; Value2: 0.1W; VDC_V: 75; TempCo: 25 ppm/C; SizeArea_mm2: 1.28; SizeX_mm: 1.6; SizeY_mm: 0.8; SizeZ_mm: 1; EIA_Code: E192; U/M: EA; AEC Category: Q200
signal-integrity model Resistor
simulation model Resistor
footprint 0603
footprint 0603M
footprint 0603L
footprint 0603_HV
footprint 0603S
pins: 1, 2

## RT0603BRD07448KL
designator R?  ValueDisplayed: 448k  (hidden comment: RT0603BRD07448KL)
RES, 448 k, 0.1%, 0.1 W, 0603; Manufacturer: Yageo America; CompType: Resistor; Value: 448k; Res_ohm: 448000; Tolerance_%: 0.1; Value2: 0.1W; VDC_V: 75; TempCo: 25 ppm/C; SizeArea_mm2: 1.28; SizeX_mm: 1.6; SizeY_mm: 0.8; SizeZ_mm: 1; EIA_Code: E192; U/M: EA; AEC Category: Q200
signal-integrity model Resistor
simulation model Resistor
footprint 0603
footprint 0603M
footprint 0603L
footprint 0603_HV
footprint 0603S
pins: 1, 2

## RT0603BRD07448RL
designator R?  ValueDisplayed: 448  (hidden comment: RT0603BRD07448RL)
RES, 448, 0.1%, 0.1 W, 0603; Manufacturer: Yageo America; CompType: Resistor; Value: 448; Value_Code: 448R; Tolerance_%: 0.1; Value2: 0.1W; VDC_V: 75; TempCo: 25 ppm/C; SizeArea_mm2: 1.28; SizeX_mm: 1.6; SizeY_mm: 0.8; SizeZ_mm: 1; EIA_Code: E192; U/M: EA; AEC Category: Q200
signal-integrity model Resistor
simulation model Resistor
footprint 0603
footprint 0603M
footprint 0603L
footprint 0603_HV
footprint 0603S
pins: 1, 2

## RT0603BRD07453KL
designator R?  ValueDisplayed: 453k  (hidden comment: RT0603BRD07453KL)
RES, 453 k, 0.1%, 0.1 W, 0603; Manufacturer: Yageo America; CompType: Resistor; Value: 453k; Res_ohm: 453000; Tolerance_%: 0.1; Value2: 0.1W; VDC_V: 75; TempCo: 25 ppm/C; SizeArea_mm2: 1.28; SizeX_mm: 1.6; SizeY_mm: 0.8; SizeZ_mm: 1; EIA_Code: E192; U/M: EA; AEC Category: Q200
signal-integrity model Resistor
simulation model Resistor
footprint 0603
footprint 0603M
footprint 0603L
footprint 0603_HV
footprint 0603S
pins: 1, 2

## RT0603BRD07453RL
designator R?  ValueDisplayed: 453  (hidden comment: RT0603BRD07453RL)
RES, 453, 0.1%, 0.1 W, 0603; Manufacturer: Yageo America; CompType: Resistor; Value: 453; Value_Code: 453R; Tolerance_%: 0.1; Value2: 0.1W; VDC_V: 75; TempCo: 25 ppm/C; SizeArea_mm2: 1.28; SizeX_mm: 1.6; SizeY_mm: 0.8; SizeZ_mm: 1; EIA_Code: E192; U/M: EA; AEC Category: Q200
signal-integrity model Resistor
simulation model Resistor
footprint 0603
footprint 0603M
footprint 0603L
footprint 0603_HV
footprint 0603S
pins: 1, 2

## RT0603BRD07459KL
designator R?  ValueDisplayed: 459k  (hidden comment: RT0603BRD07459KL)
RES, 459 k, 0.1%, 0.1 W, 0603; Manufacturer: Yageo America; CompType: Resistor; Value: 459k; Res_ohm: 459000; Tolerance_%: 0.1; Value2: 0.1W; VDC_V: 75; TempCo: 25 ppm/C; SizeArea_mm2: 1.28; SizeX_mm: 1.6; SizeY_mm: 0.8; SizeZ_mm: 1; EIA_Code: E192; U/M: EA; AEC Category: Q200
signal-integrity model Resistor
simulation model Resistor
footprint 0603
footprint 0603M
footprint 0603L
footprint 0603_HV
footprint 0603S
pins: 1, 2

## RT0603BRD07459RL
designator R?  ValueDisplayed: 459  (hidden comment: RT0603BRD07459RL)
RES, 459, 0.1%, 0.1 W, 0603; Manufacturer: Yageo America; CompType: Resistor; Value: 459; Value_Code: 459R; Tolerance_%: 0.1; Value2: 0.1W; VDC_V: 75; TempCo: 25 ppm/C; SizeArea_mm2: 1.28; SizeX_mm: 1.6; SizeY_mm: 0.8; SizeZ_mm: 1; EIA_Code: E192; U/M: EA; AEC Category: Q200
signal-integrity model Resistor
simulation model Resistor
footprint 0603
footprint 0603M
footprint 0603L
footprint 0603_HV
footprint 0603S
pins: 1, 2

## RT0603BRD07464KL
designator R?  ValueDisplayed: 464k  (hidden comment: RT0603BRD07464KL)
RES, 464 k, 0.1%, 0.1 W, 0603; Manufacturer: Yageo America; CompType: Resistor; Value: 464k; Res_ohm: 464000; Tolerance_%: 0.1; Value2: 0.1W; VDC_V: 75; TempCo: 25 ppm/C; SizeArea_mm2: 1.28; SizeX_mm: 1.6; SizeY_mm: 0.8; SizeZ_mm: 1; EIA_Code: E192; U/M: EA; AEC Category: Q200
signal-integrity model Resistor
simulation model Resistor
footprint 0603
footprint 0603M
footprint 0603L
footprint 0603_HV
footprint 0603S
pins: 1, 2

## RT0603BRD07464RL
designator R?  ValueDisplayed: 464  (hidden comment: RT0603BRD07464RL)
RES, 464, 0.1%, 0.1 W, 0603; Manufacturer: Yageo America; CompType: Resistor; Value: 464; Value_Code: 464R; Tolerance_%: 0.1; Value2: 0.1W; VDC_V: 75; TempCo: 25 ppm/C; SizeArea_mm2: 1.28; SizeX_mm: 1.6; SizeY_mm: 0.8; SizeZ_mm: 1; EIA_Code: E192; U/M: EA; AEC Category: Q200
signal-integrity model Resistor
simulation model Resistor
footprint 0603
footprint 0603M
footprint 0603L
footprint 0603_HV
footprint 0603S
pins: 1, 2

## RT0603BRD07470KL
designator R?  ValueDisplayed: 470k  (hidden comment: RT0603BRD07470KL)
RES, 470 k, 0.1%, 0.1 W, 0603; Manufacturer: Yageo America; CompType: Resistor; Value: 470k; Res_ohm: 470000; Tolerance_%: 0.1; Value2: 0.1W; VDC_V: 75; TempCo: 25 ppm/C; SizeArea_mm2: 1.28; SizeX_mm: 1.6; SizeY_mm: 0.8; SizeZ_mm: 1; EIA_Code: E192; U/M: EA; AEC Category: Q200
signal-integrity model Resistor
simulation model Resistor
footprint 0603
footprint 0603M
footprint 0603L
footprint 0603_HV
footprint 0603S
pins: 1, 2

## RT0603BRD07470RL
designator R?  ValueDisplayed: 470  (hidden comment: RT0603BRD07470RL)
RES, 470, 0.1%, 0.1 W, 0603; Manufacturer: Yageo America; CompType: Resistor; Value: 470; Value_Code: 470R; Tolerance_%: 0.1; Value2: 0.1W; VDC_V: 75; TempCo: 25 ppm/C; SizeArea_mm2: 1.28; SizeX_mm: 1.6; SizeY_mm: 0.8; SizeZ_mm: 1; EIA_Code: E192; U/M: EA; AEC Category: Q200
signal-integrity model Resistor
simulation model Resistor
footprint 0603
footprint 0603M
footprint 0603L
footprint 0603_HV
footprint 0603S
pins: 1, 2

## RT0603BRD07475KL
designator R?  ValueDisplayed: 475k  (hidden comment: RT0603BRD07475KL)
RES, 475 k, 0.1%, 0.1 W, 0603; Manufacturer: Yageo America; CompType: Resistor; Value: 475k; Res_ohm: 475000; Tolerance_%: 0.1; Value2: 0.1W; VDC_V: 75; TempCo: 25 ppm/C; SizeArea_mm2: 1.28; SizeX_mm: 1.6; SizeY_mm: 0.8; SizeZ_mm: 1; EIA_Code: E192; U/M: EA; AEC Category: Q200
signal-integrity model Resistor
simulation model Resistor
footprint 0603
footprint 0603M
footprint 0603L
footprint 0603_HV
footprint 0603S
pins: 1, 2

## RT0603BRD07475RL
designator R?  ValueDisplayed: 475  (hidden comment: RT0603BRD07475RL)
RES, 475, 0.1%, 0.1 W, 0603; Manufacturer: Yageo America; CompType: Resistor; Value: 475; Value_Code: 475R; Tolerance_%: 0.1; Value2: 0.1W; VDC_V: 75; TempCo: 25 ppm/C; SizeArea_mm2: 1.28; SizeX_mm: 1.6; SizeY_mm: 0.8; SizeZ_mm: 1; EIA_Code: E192; U/M: EA; AEC Category: Q200
signal-integrity model Resistor
simulation model Resistor
footprint 0603
footprint 0603M
footprint 0603L
footprint 0603_HV
footprint 0603S
pins: 1, 2

## RT0603BRD07481KL
designator R?  ValueDisplayed: 481k  (hidden comment: RT0603BRD07481KL)
RES, 481 k, 0.1%, 0.1 W, 0603; Manufacturer: Yageo America; CompType: Resistor; Value: 481k; Res_ohm: 481000; Tolerance_%: 0.1; Value2: 0.1W; VDC_V: 75; TempCo: 25 ppm/C; SizeArea_mm2: 1.28; SizeX_mm: 1.6; SizeY_mm: 0.8; SizeZ_mm: 1; EIA_Code: E192; U/M: EA; AEC Category: Q200
signal-integrity model Resistor
simulation model Resistor
footprint 0603
footprint 0603M
footprint 0603L
footprint 0603_HV
footprint 0603S
pins: 1, 2

## RT0603BRD07481RL
designator R?  ValueDisplayed: 481  (hidden comment: RT0603BRD07481RL)
RES, 481, 0.1%, 0.1 W, 0603; Manufacturer: Yageo America; CompType: Resistor; Value: 481; Value_Code: 481R; Tolerance_%: 0.1; Value2: 0.1W; VDC_V: 75; TempCo: 25 ppm/C; SizeArea_mm2: 1.28; SizeX_mm: 1.6; SizeY_mm: 0.8; SizeZ_mm: 1; EIA_Code: E192; U/M: EA; AEC Category: Q200
signal-integrity model Resistor
simulation model Resistor
footprint 0603
footprint 0603M
footprint 0603L
footprint 0603_HV
footprint 0603S
pins: 1, 2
